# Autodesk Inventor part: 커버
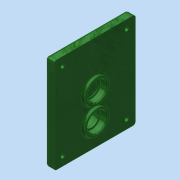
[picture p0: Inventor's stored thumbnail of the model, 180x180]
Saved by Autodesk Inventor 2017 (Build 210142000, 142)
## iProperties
Created: 2016-02
Part Number: 커버
Material: 알루미늄 6061
Document SubType Name: Modeling
Designer: mduedu
Density: 2.71 g/cm^3
Mass: 271.622 g
Surface Area: 265.357 cm^2
Volume: 100.23 cm^3
Appearance: 매끄러움 - 짙은 산림 녹색
Author: mduedu
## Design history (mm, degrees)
sketch "스케치1"
  geometry: L1 (63, 47)-(-47, 47); L2 (-47, 47)-(-47, -47); L3 (-47, -47)-(63, -47); L4 (63, -47)-(63, 47); 2 further points
  constraints: 8 end point, 2 parallel, 1 horizontal, 1 horizontal alignment, 1 midpoint, 1 perpendicular
  dimensions: "d102" = 94 distance of L3.end L1.start; "d104" = 47 distance from line of L2 point (0, 0); "d105" = 110 distance of L1.start L1.end
extrude "돌출1" new body sketch "스케치1" distance "d1" = 10; taper "d2" = 0 deg
sketch "스케치2"
  geometry: C1 r 14 at (0, 11); 1 further point
  constraints: 1 centre point, 1 vertical alignment
  dimensions: "d3" = 28 diameter of C1; "d6" = 11 distance of C1.centre point (0, 0)
extrude "돌출2" join sketch "스케치2" distance "d7" = 3; taper "d8" = 0 deg
sketch "스케치3"
  geometry: C1 r 14 at (0, -20); 1 further point
  constraints: 1 centre point, 1 vertical alignment
  dimensions: "d9" = 28 diameter of C1; "d10" = 20 distance of C1.centre point (0, 0)
extrude "돌출3" join sketch "스케치3" distance "d11" = 3; taper "d12" = 0 deg
hole "구멍1" diameter "d15" = 22; stored, may be unused: countersink angle "d19" = 90 deg, drill point angle "d21" = 0 deg; dims "d13" = 10, "d14" = 10, "d16" = 6, "d17" = 4, "d18" = 2, "d20" = 7
hole "구멍2" diameter "d24" = 18; stored, may be unused: countersink angle "d28" = 90 deg, drill point angle "d30" = 0 deg; dims "d22" = 10, "d23" = 10, "d25" = 6, "d26" = 4, "d27" = 2, "d29" = 1
hole "구멍3" diameter "d33" = 22; stored, may be unused: countersink angle "d37" = 90 deg, drill point angle "d39" = 0 deg; dims "d34" = 6, "d35" = 4, "d36" = 2, "d38" = 7, "d73" = 10, "d74" = 10
sketch "스케치4"
  geometry: C1 r 14 at (0, -20) reference; C2 r 18 at (0, -20); 1 further point
  constraints: 1 centre point, 1 coincident
  dimensions: "d40" = 36 diameter of C2
extrude "돌출4" join sketch "스케치4" distance "d41" = 4; taper "d42" = 0 deg
hole "구멍4" diameter "d45" = 22; stored, may be unused: countersink angle "d49" = 90 deg, drill point angle "d51" = 0 deg; dims "d43" = 10, "d44" = 10, "d46" = 6, "d47" = 4, "d48" = 2, "d50" = 7
hole "구멍5" diameter "d54" = 18; stored, may be unused: countersink angle "d58" = 90 deg, drill point angle "d60" = 0 deg; dims "d55" = 6, "d56" = 4, "d57" = 2, "d59" = 7, "d116" = 10, "d117" = 10
fillet "모깎기1" dims "d61" = 0.3
fillet "모깎기2" dims "d62" = 2
chamfer "모따기1" distance "d63" = 1; stored, may be unused: second distance "d64" = 2, angle "d65" = 45 deg
fillet "모깎기6" dims "d88" = 2
fillet "모깎기4" dims "d75" = 2
sketch "스케치9"
  geometry: L1 (47, 63)-(47, -47) reference; L2 (-47, 63)-(47, 63) reference; L3 (-47, -47)-(-47, 63) reference; L4 (47, -47)-(-47, -47) reference; L5 (37, 53)-(37, -37); L6 (37, -37)-(-37, -37); L7 (-37, -37)-(-37, 53); L8 (-37, 53)-(37, 53); C1 r 20 at (0, -20) reference; 5 further points
  constraints: 8 end point, 4 coincident, 3 other
  dimensions: "d107" = 10 distance between parallel lines of L8 L2
hole "구멍7" sketch "스케치9" at (-37, 53), (37, 53), (37, -37), (-37, -37) diameter "d108" = 4.5; stored, may be unused: countersink angle "d112" = 90 deg, drill point angle "d114" = 118 deg; dims "d109" = 6, "d110" = 8, "d111" = 4.6, "d113" = 8
fillet "모깎기8" dims "d106" = 3
fillet "모깎기9" dims "d115" = 3
node "솔리드1"
node "투영된 루프2"
